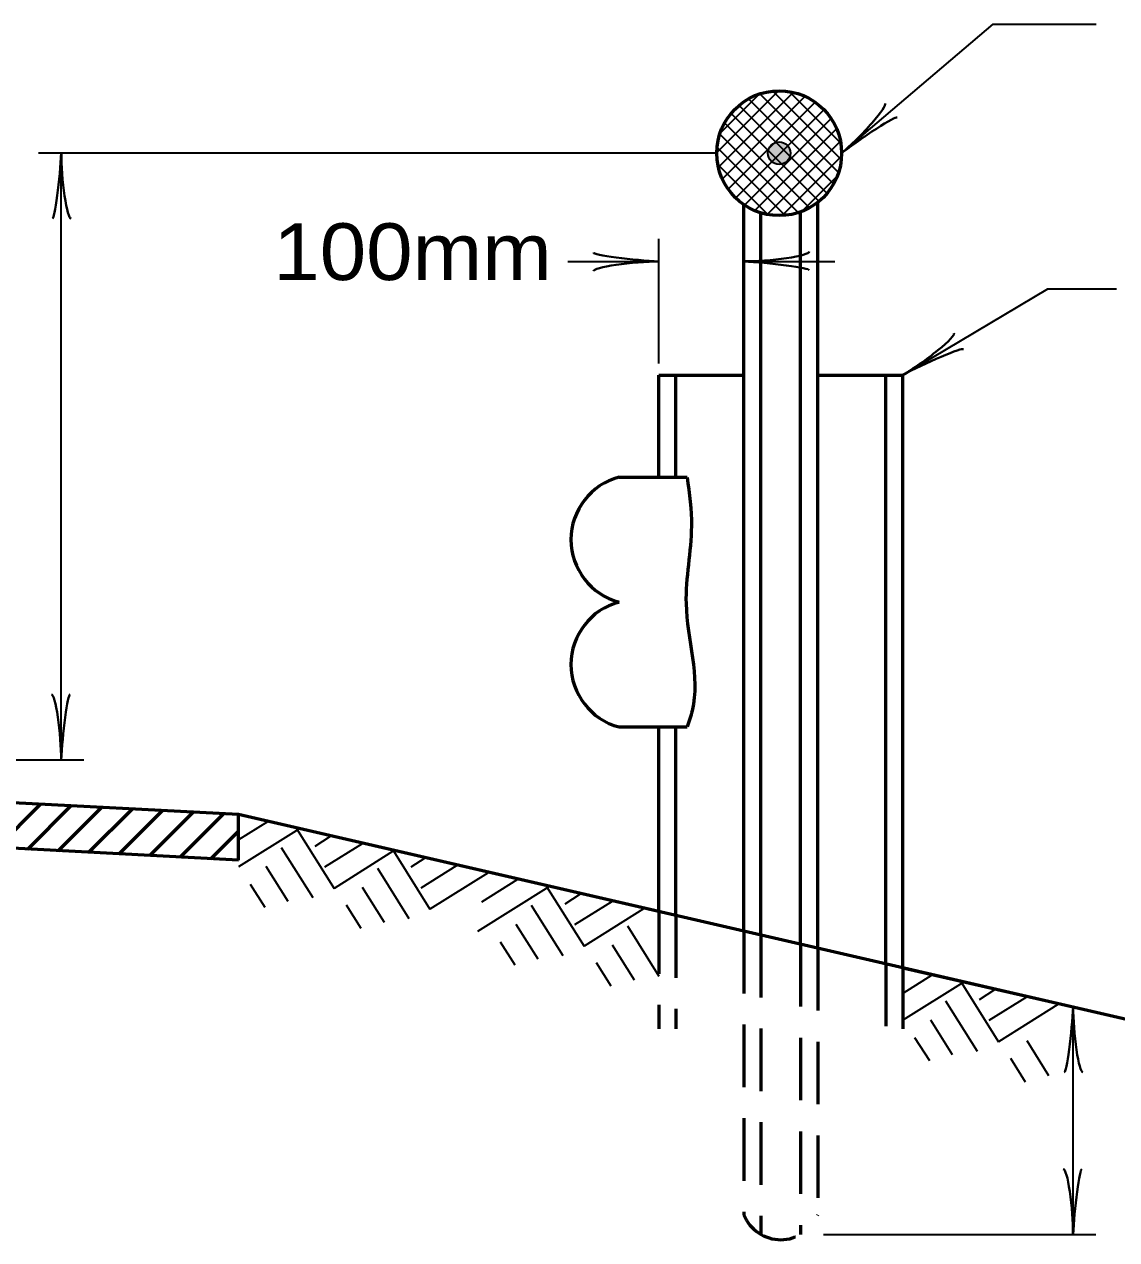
# Model space of a CAD drawing. Extents: x -89 to 766, y -60 to 484.
# Drawn here: x 157.5 to 215.2, y 20.6 to 84.8 of the extents above; entities that cross this region are included whole.
import ezdxf

# ---------------------------------------------------------------- set-up
doc = ezdxf.new("R2010")
doc.units = 0
doc.header["$LTSCALE"] = 1.1
doc.linetypes.add('MEDIUM_DASHED', pattern=[4.5, 3, -1.5])
doc.layers.add('1', color=7, linetype='Continuous', lineweight=35)

msp = doc.modelspace()

# ---------------------------------------------------------------- hatches: boundary and pattern name
at = {"layer": '1'}
msp.add_hatch(color=256, dxfattribs=at).paths.add_polyline_path([(197.957, 77.975, 1), (196.757, 77.975, 1)])

# ---------------------------------------------------------------- linework, layer by layer
for p, q in [((194.058, 78.01), (197.321, 81.273)), ((194.141, 77.244), (198.087, 81.19)), ((194.238, 79.038), (196.295, 81.095)), ((194.358, 76.612), (198.72, 80.974)), ((200.487, 76.949), (196.33, 81.106)), ((200.636, 77.649), (197.029, 81.256)), ((200.604, 78.529), (197.91, 81.223)), ((194.665, 76.071), (199.262, 80.668)), ((199.881, 75.858), (195.238, 80.501)), ((200.23, 76.358), (195.74, 80.847)), ((199.886, 80.129), (199.529, 80.485)), ((199.456, 75.434), (194.817, 80.074)), ((195.058, 75.615), (199.716, 80.274)), ((195.526, 75.235), (200.099, 79.808)), ((198.951, 75.091), (194.471, 79.571)), ((196.078, 74.938), (200.394, 79.254)), ((198.357, 74.837), (194.218, 78.975)), ((196.73, 74.742), (200.591, 78.603)), ((194.057, 77.975), (158.212, 77.975)), ((159.412, 45.918), (159.412, 77.975)), ((197.652, 74.693), (194.075, 78.27)), ((197.522, 74.686), (200.647, 77.811)), ((196.761, 74.736), (194.117, 77.379)), ((198.644, 74.985), (200.434, 76.775)), ((190.991, 66.853), (190.991, 73.453)), ((186.191, 72.253), (190.991, 72.253)), ((195.491, 72.253), (200.291, 72.253)), ((115.532, 45.918), (160.612, 45.918)), ((170.307, 42.638), (168.776, 41.681)), ((171.968, 42.254), (168.776, 40.26)), ((171.851, 42.281), (173.829, 39.115)), ((173.628, 41.871), (172.817, 41.344)), ((171.03, 41.288), (172.708, 38.635)), ((175.312, 41.482), (173.326, 40.241)), ((176.972, 41.099), (173.829, 39.115)), ((176.972, 41.099), (178.896, 38.019)), ((178.632, 40.715), (177.884, 40.248)), ((170.233, 40.29), (171.384, 38.448)), ((176.121, 40.187), (177.776, 37.539)), ((180.316, 40.327), (178.416, 39.14)), ((181.976, 39.944), (178.896, 38.019)), ((169.4, 39.349), (170.179, 38.135)), ((175.324, 39.189), (176.475, 37.346)), ((185.18, 39.204), (181.409, 36.848)), ((183.52, 39.587), (181.62, 38.4)), ((185.063, 39.231), (187.042, 36.065)), ((186.84, 38.821), (186.029, 38.294)), ((174.468, 38.253), (175.241, 37.016)), ((184.243, 38.238), (185.921, 35.584)), ((188.524, 38.432), (186.538, 37.191)), ((190.184, 38.049), (187.042, 36.065)), ((183.446, 37.24), (184.597, 35.398)), ((189.333, 37.137), (190.991, 34.483)), ((182.613, 36.299), (183.392, 35.085)), ((188.536, 36.138), (189.688, 34.296)), ((187.68, 35.203), (188.454, 33.965)), ((205.424, 34.53), (203.891, 33.573)), ((207.084, 34.147), (203.891, 32.152)), ((206.967, 34.174), (208.946, 31.008)), ((208.745, 33.764), (207.933, 33.237)), ((206.147, 33.181), (207.825, 30.528)), ((210.428, 33.375), (208.442, 32.134)), ((212.089, 32.992), (208.946, 31.008)), ((212.891, 20.838), (212.891, 32.855)), ((205.35, 32.183), (206.501, 30.341)), ((204.517, 31.242), (205.296, 30.028)), ((210.441, 31.081), (211.592, 29.239)), ((209.584, 30.146), (210.358, 28.908)), ((199.691, 20.838), (214.091, 20.838))]:
    msp.add_line(p, q, dxfattribs=at)
at = {"layer": '1', "lineweight": 53}
for p, q in [((195.491, 36.873), (195.491, 75.253)), ((199.391, 35.972), (199.391, 75.377)), ((196.391, 36.665), (196.391, 74.82)), ((198.491, 36.18), (198.491, 74.877)), ((190.991, 66.253), (195.491, 66.253)), ((190.991, 60.853), (190.991, 66.253)), ((191.891, 60.853), (191.891, 66.253)), ((199.391, 66.253), (203.891, 66.253)), ((202.991, 35.141), (202.991, 66.253)), ((203.891, 34.933), (203.891, 66.253)), ((188.891, 60.853), (192.491, 60.853)), ((188.891, 47.653), (192.491, 47.653)), ((190.991, 37.912), (190.991, 47.653)), ((191.891, 37.704), (191.891, 47.653)), ((112.579, 45.97), (168.776, 43.041)), ((168.776, 40.615), (112.579, 43.56)), ((156.03, 41.283), (158.332, 43.585)), ((157.642, 41.198), (159.945, 43.501)), ((159.255, 41.114), (161.558, 43.417)), ((160.867, 41.029), (163.171, 43.333)), ((162.48, 40.945), (164.784, 43.249)), ((164.093, 40.86), (166.397, 43.165)), ((165.705, 40.776), (168.01, 43.08)), ((168.775, 43.041), (190.991, 37.912)), ((168.776, 40.615), (168.776, 43.041)), ((168.776, 43.04), (211.82, 33.103)), ((167.318, 40.691), (168.776, 42.149))]:
    msp.add_line(p, q, dxfattribs=at)
at = {"layer": '1', "linetype": 'MEDIUM_DASHED', "lineweight": 53}
for p, q in [((190.991, 37.912), (190.991, 31.704)), ((191.891, 37.704), (191.891, 31.704)), ((195.491, 36.873), (195.491, 21.873)), ((196.391, 36.665), (196.391, 20.838)), ((198.491, 36.18), (198.491, 20.838)), ((199.391, 35.972), (199.391, 21.873)), ((202.991, 35.141), (202.991, 31.704)), ((203.891, 34.933), (203.891, 31.704))]:
    msp.add_line(p, q, dxfattribs=at)
at = {"layer": '1'}
for points in [[(200.657, 77.975), (208.665, 84.786), (214.115, 84.786)], [(203.891, 66.253), (211.553, 70.806), (215.184, 70.806)]]:
    msp.add_lwpolyline(points, dxfattribs=at)
at = {"layer": '1', "lineweight": 53}
msp.add_lwpolyline([(203.891, 34.933), (211.82, 33.103), (255.163, 23.096)], dxfattribs=at)
msp.add_circle((197.357, 77.975), 3.3, dxfattribs=at)
at = {"layer": '1'}
msp.add_circle((197.357, 77.975), 0.6, dxfattribs=at)
at = {"layer": '1', "lineweight": 53}
for centre in [(189.765, 57.553), (189.765, 50.953)]:
    msp.add_arc(centre, 3.414, 104.83216, 255.16784, dxfattribs=at)
at = {"layer": '1', "linetype": 'MEDIUM_DASHED', "lineweight": 53}
msp.add_arc((197.441, 22.661), 2.103, 202.01371, 337.98629, dxfattribs=at)
at = {"layer": '1', "lineweight": 40}
for centre, major_axis, ratio, start_param, end_param in [((201.44, 79.076), (-1.511, -1.531), 0.122415, 0.896353, 3.141593), ((201.44, 79.076), (-1.511, -1.531), 0.122415, 0.896353, 3.141593), ((201.846, 78.653), (-1.742, -1.205), 0.07063, 3.140715, 5.41811), ((201.846, 78.653), (-1.742, -1.205), 0.07063, 3.140715, 5.41811), ((159.158, 76.631), (0.211, 2.108), 0.07063, 3.140715, 5.41811), ((159.743, 76.666), (-0.187, 2.143), 0.122415, 0.896353, 3.141593), ((189.647, 72.507), (2.108, -0.211), 0.07063, 3.140715, 5.41811), ((189.647, 72.507), (2.108, -0.211), 0.07063, 3.140715, 5.41811), ((196.801, 72.585), (-2.143, -0.187), 0.122415, 0.896353, 3.141593), ((189.682, 71.922), (2.143, 0.187), 0.122415, 0.896353, 3.141593), ((189.682, 71.922), (2.143, 0.187), 0.122415, 0.896353, 3.141593), ((196.836, 71.999), (-2.108, 0.211), 0.07063, 3.140715, 5.41811), ((204.848, 67.207), (-1.746, -1.256), 0.122415, 0.896353, 3.141593), ((205.177, 66.722), (-1.92, -0.895), 0.07063, 3.140715, 5.41811), ((159.08, 47.227), (0.187, -2.143), 0.122415, 0.896353, 3.141593), ((159.666, 47.263), (-0.211, -2.108), 0.07063, 3.140715, 5.41811), ((212.637, 31.511), (0.211, 2.108), 0.07063, 3.140715, 5.41811), ((212.637, 31.511), (0.211, 2.108), 0.07063, 3.140715, 5.41811), ((213.223, 31.546), (-0.187, 2.143), 0.122415, 0.896353, 3.141593), ((213.223, 31.546), (-0.187, 2.143), 0.122415, 0.896353, 3.141593), ((212.56, 22.148), (0.187, -2.143), 0.122415, 0.896353, 3.141593), ((213.145, 22.183), (-0.211, -2.108), 0.07063, 3.140715, 5.41811)]:
    msp.add_ellipse(centre, major_axis=major_axis, ratio=ratio, start_param=start_param, end_param=end_param, dxfattribs=at)
at = {"layer": '1', "lineweight": 53}
msp.add_spline([(192.491, 60.853), (192.718, 58.269), (192.434, 54.173), (192.754, 48.51), (192.491, 47.653)], degree=3, dxfattribs=at)

# ---------------------------------------------------------------- texts
at = {"layer": '1', "width": 1.1}
msp.add_text('100mm', height=3, dxfattribs=at).set_placement((170.62, 71.27))

doc.saveas('drawing.dxf')
